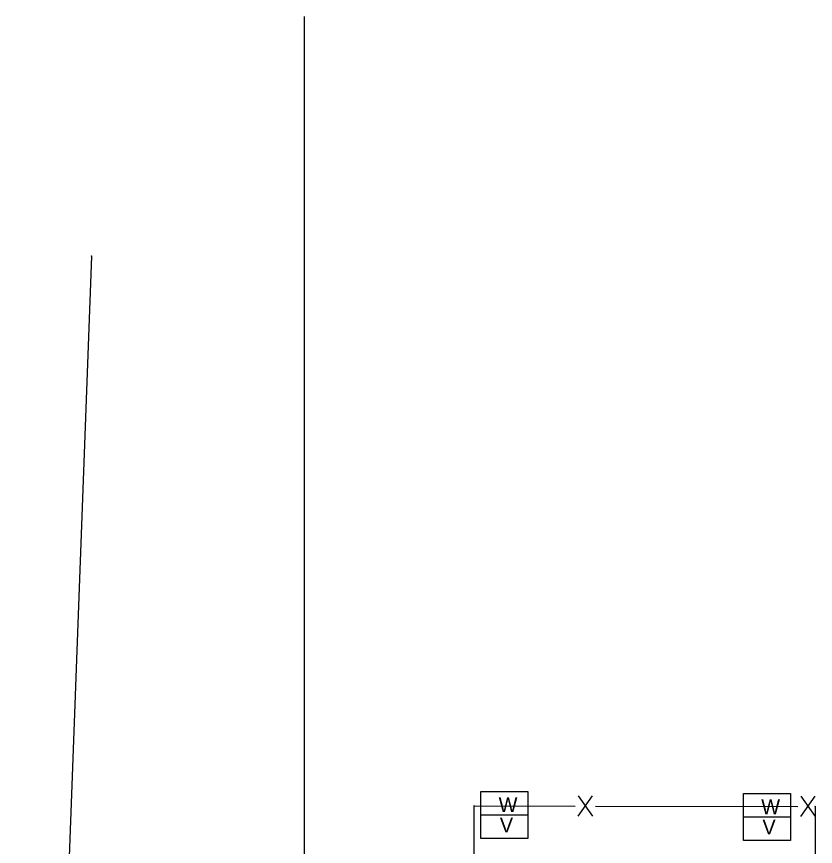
# Model space of a CAD drawing. Extents: x 1707085 to 1720058, y 548761 to 560063.
# Drawn here: x 1712456.2 to 1712616.1, y 551149.9 to 551316 of the extents above; entities that cross this region are included whole.
import ezdxf

# ---------------------------------------------------------------- set-up
doc = ezdxf.new("R2010")
doc.units = 0
for name, color, linetype in [('R_Contours', 7, 'Continuous'), ('R_Water Annot', 7, 'Continuous'), ('S_GAS_UTILITIES', 7, 'Continuous'), ('S_MSC_PT_SYM', 7, 'Continuous'), ('S_UTILITY_POLE', 7, 'Continuous'), ('S_UTL_PT_SYM', 7, 'Continuous')]:
    doc.layers.add(name, color=color, linetype=linetype)

msp = doc.modelspace()

# ---------------------------------------------------------------- linework, layer by layer
at = {"layer": 'R_Contours'}
for p, q in [((1712568.66, 551155.9), (1712571.52, 551159.99)), ((1712568.67, 551159.99), (1712571.52, 551155.9)), ((1712613.2, 551155.85), (1712616.06, 551159.94)), ((1712613.2, 551159.94), (1712616.06, 551155.84))]:
    msp.add_line(p, q, dxfattribs=at)
for points in [[(1712547.8, 551140.62), (1712547.82, 551157.97)], [(1712547.82, 551157.97), (1712568.07, 551157.95)], [(1712572.12, 551157.94), (1712612.61, 551157.89)], [(1712616.08, 551157.89), (1712615.99, 551137.44)]]:
    msp.add_lwpolyline(points, dxfattribs=at)
at = {"layer": 'R_Water Annot'}
for p, q in [((1712549.17, 551160.88), (1712558.59, 551160.88)), ((1712549.17, 551151.47), (1712549.17, 551160.88)), ((1712558.59, 551160.88), (1712558.59, 551151.47)), ((1712601.73, 551160.48), (1712611.15, 551160.48)), ((1712601.73, 551151.06), (1712601.73, 551160.48)), ((1712611.15, 551160.48), (1712611.15, 551151.06)), ((1712549.17, 551156.19), (1712558.59, 551156.19)), ((1712601.73, 551155.79), (1712611.15, 551155.79)), ((1712558.59, 551151.47), (1712549.17, 551151.47)), ((1712611.15, 551151.06), (1712601.73, 551151.06))]:
    msp.add_line(p, q, dxfattribs=at)
at = {"layer": 'S_GAS_UTILITIES'}
msp.add_line((1712471.24, 551268.07), (1712456.25, 550862.48), dxfattribs=at)
at = {"layer": 'S_MSC_PT_SYM'}
for points in [[(1712547.82, 551157.97), (1712547.82, 551158.02), (1712547.82, 551157.97), (1712547.77, 551157.97), (1712547.82, 551157.97), (1712547.82, 551157.92), (1712547.82, 551157.97), (1712547.87, 551157.97)], [(1712616.08, 551157.89), (1712616.08, 551157.94), (1712616.08, 551157.89), (1712616.03, 551157.89), (1712616.08, 551157.89), (1712616.08, 551157.84), (1712616.08, 551157.89), (1712616.13, 551157.89)]]:
    msp.add_lwpolyline(points, dxfattribs=at)
at = {"layer": 'S_UTILITY_POLE'}
msp.add_line((1712513.87, 551133.13), (1712513.87, 551316), dxfattribs=at)
at = {"layer": 'S_UTL_PT_SYM'}
msp.add_lwpolyline([(1712471.24, 551268.07), (1712471.24, 551268.12), (1712471.24, 551268.07), (1712471.19, 551268.07), (1712471.24, 551268.07), (1712471.24, 551268.02), (1712471.24, 551268.07), (1712471.29, 551268.07)], dxfattribs=at)

# ---------------------------------------------------------------- texts
at = {"layer": 'R_Water Annot'}
for s, p in [('W', (1712552.72, 551156.73)), ('W', (1712605.28, 551156.32)), ('V', (1712552.96, 551152.66)), ('V', (1712605.52, 551152.26))]:
    msp.add_text(s, height=3, rotation=360, dxfattribs=at).set_placement(p)

doc.saveas('drawing.dxf')
